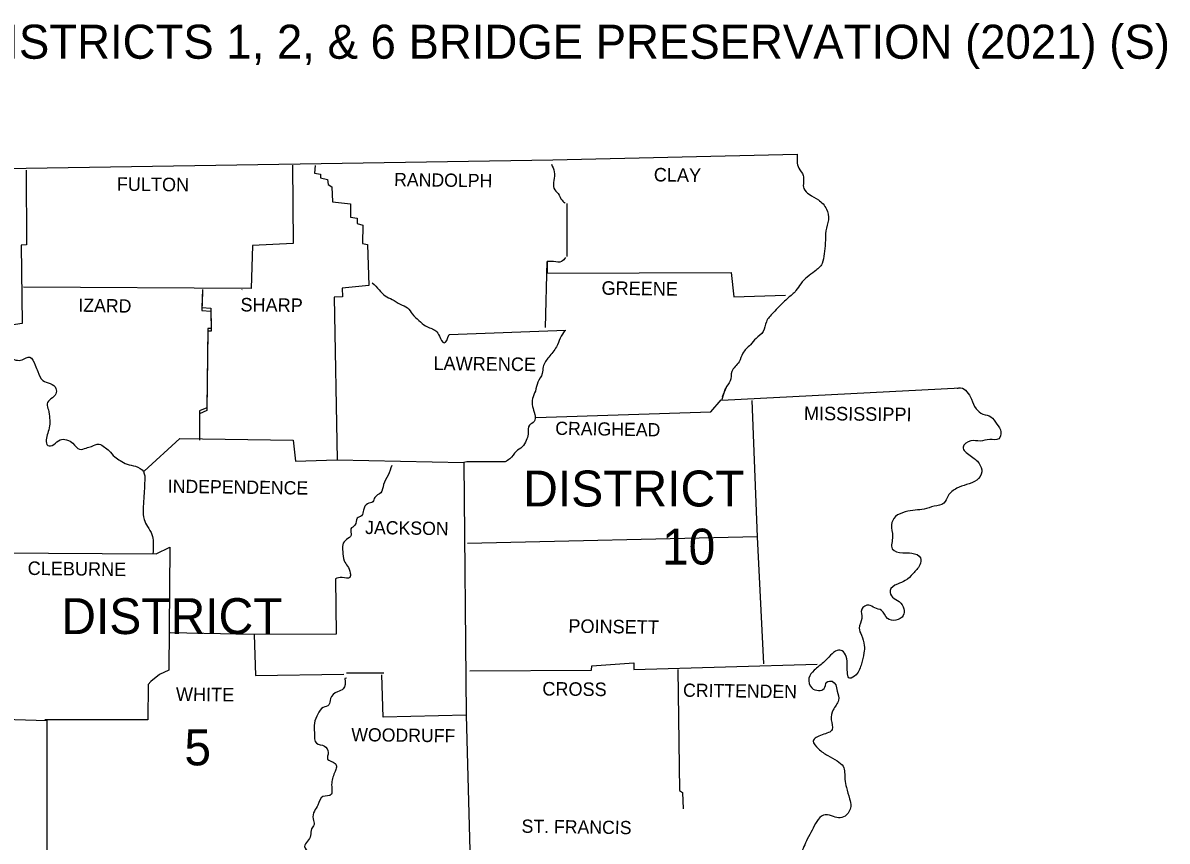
# Model space of a CAD drawing. Extents: x -31696 to 27919, y -8775 to 11152.
# Drawn here: x 13726 to 17282, y 8206 to 10749 of the extents above; entities that cross this region are included whole.
import ezdxf

# ---------------------------------------------------------------- set-up
doc = ezdxf.new("R2010")
doc.units = 0
for name, color, linetype in [('Level 1', 7, 'Continuous'), ('Level 2', 7, 'Continuous'), ('Level 3', 7, 'Continuous'), ('Level 42', 7, 'Continuous')]:
    doc.layers.add(name, color=color, linetype=linetype)

msp = doc.modelspace()

# ---------------------------------------------------------------- linework, layer by layer
at = {"layer": 'Level 1'}
for p, q in [((15897.8, 9576.2), (15909.5, 9612.4)), ((15900.7, 9588), (15912.5, 9616.3)), ((14731.5, 8728.9), (14848, 8728.9))]:
    msp.add_line(p, q, dxfattribs=at)
for points in [[(10765.1, 10295.4), (12347.2, 10294.4), (13735.5, 10297.3), (15373.4, 10322.8), (16132.6, 10340.4)], [(13735.5, 10291.4), (13737.5, 10058.6), (13720.8, 10057.6), (13723.8, 9814), (13655.3, 9804.2), (13661.2, 9738.6), (13684.6, 9708.3), (13682.7, 9631), (13549.6, 9626.1), (13544.7, 9506.8), (13423.4, 9502.9), (13417.5, 9358), (13424.4, 9346.3), (13427.3, 9115.4), (13636.7, 9101.7), (13633.8, 8586.1), (13800.1, 8581.2), (13800.1, 8056.8), (13669, 8047), (13659.2, 7931.5), (13439.1, 7930.6)], [(14564.2, 10306.1), (14566.2, 10063.5), (14439, 10056.6), (14435.1, 9923.6), (13727.7, 9927.5)], [(14634.7, 10305.1), (14631.7, 10281.7), (14651.3, 10278.7), (14650.3, 10267), (14672.8, 10262.1), (14674.8, 10246.4), (14685.5, 10239.6), (14688.5, 10192.6), (14744.3, 10186.8), (14744.3, 10144.7), (14764.8, 10141.8), (14764.8, 10125.1), (14782.4, 10120.2), (14781.4, 10063.5), (14797.1, 10060.5), (14801, 9932.4), (14717.8, 9924.5), (14718.8, 9897.2), (14693.4, 9896.2), (14702.2, 9391.3), (15096.5, 9382.5), (15103.3, 8597.8), (14846, 8591), (14841.1, 8723.1)], [(15416.4, 10187.7), (15416.4, 10022.4)], [(15349.9, 9802.2), (15354.8, 10006.7), (15354.8, 9970.5), (15927.1, 9973.5), (15935, 9897.2), (16096.4, 9903)], [(14284.4, 9920.6), (14282.4, 9863.9), (14309.8, 9861.9), (14310.8, 9799.3), (14301, 9799.3), (14297.1, 9552.8), (14274.6, 9543), (14274.6, 9460.8)], [(14284.4, 9911.8), (14282.4, 9855.1), (14309.8, 9853.1), (14310.8, 9790.5), (14301, 9790.5), (14297.1, 9543.9), (14274.6, 9534.2), (14274.6, 9452)], [(14406.7, 9918.7), (14407.7, 9919.7)], [(15050.5, 9780.7), (15413.5, 9793.4)], [(15897.8, 9576.2), (16640.4, 9614.4)], [(15320.5, 9522.4), (15863.5, 9540), (15895.8, 9577.2)], [(15991.7, 9575.3), (16008.4, 9151.6), (16027.9, 8757.3)], [(14102.4, 9356.1), (14214, 9456.9), (14566.2, 9452), (14573, 9386.4), (14701.2, 9391.3)], [(15224.6, 9384.5), (15105.3, 9384.5), (15096.5, 9382.5)], [(16008.4, 9151.6), (15107.2, 9131.1)], [(13636.7, 9101.7), (14139.6, 9098.8), (14182.6, 9119.3), (14179.7, 8736.8), (14150.4, 8724), (14123.9, 8701.5), (14115.1, 8692.7), (14114.2, 8583.2), (13794.2, 8583.2)], [(14697.3, 9021.5), (14699.2, 8849.3), (14444.9, 8848.3), (14183.6, 8853.2)], [(14444.9, 8848.3), (14448.8, 8720.1), (14723.7, 8725)], [(15115.1, 8734.8), (15492.7, 8736.8), (15493.7, 8750.5), (15624.8, 8760.2), (15624.8, 8739.7), (16194.2, 8755.4)], [(15761.8, 8739.7), (15766.7, 8363), (15775.5, 8357.1), (15778.4, 8306.3)], [(14731.5, 8712.3), (14726.6, 8711.3)], [(15103.3, 8597.8), (15118, 8061.7), (14885.1, 8060.7), (14884.2, 8039.2), (14816.7, 8035.2), (14810.8, 7923.7), (14728.6, 7923.7)]]:
    msp.add_lwpolyline(points, dxfattribs=at)
for points in [[(16132.6, 10340.4), (16137.5, 10297.3), (16151.2, 10274.8), (16153.2, 10233.7), (16169.8, 10216.1), (16198.2, 10198.5), (16223.6, 10170.1), (16229.5, 10136.9), (16221.6, 10102.6), (16219.7, 10064.5), (16215.8, 10031.2), (16209.9, 10000.9), (16186.4, 9976.4), (16163.9, 9958.8), (16143.4, 9938.2), (16128.7, 9916.7), (16103.3, 9893.2), (16077.8, 9868.8), (16057.3, 9847.3), (16036.7, 9819.9), (16026.9, 9789.5), (16004.4, 9768), (15986.8, 9748.4), (15963.3, 9722), (15951.6, 9695.6), (15929.1, 9665.3), (15924.2, 9635.9), (15909.5, 9612.4), (15908.6, 9608.5)], [(15368.5, 10310), (15377.3, 10285.6), (15376.3, 10259.2), (15376.3, 10234.7), (15389, 10218.1), (15401.7, 10197.5), (15411.5, 10188.7)], [(15412.5, 10019.5), (15399.8, 10006.7), (15375.3, 10006.7), (15354.8, 10006.7)], [(14811.8, 9941.2), (14833.3, 9918.7), (14851.9, 9900.1), (14873.4, 9889.3), (14898.8, 9874.6), (14921.3, 9862.9), (14936, 9844.3), (14956.6, 9823.8), (14977.1, 9807.1), (15009.4, 9791.5), (15020.2, 9774.9), (15034.8, 9754.3), (15050.5, 9780.7)], [(15410.5, 9792.5), (15395.9, 9769), (15384.1, 9741.6), (15360.6, 9710.3), (15343, 9679.9), (15340.1, 9659.4), (15326.4, 9632), (15318.6, 9604.6), (15309.8, 9581.1), (15309.8, 9556.7), (15316.6, 9532.2), (15314.7, 9509.7), (15300, 9498.9), (15296.1, 9470.6), (15290.2, 9451), (15277.5, 9431.4), (15258.9, 9416.8), (15239.3, 9394.2), (15224.6, 9384.5)], [(13684.6, 9708.3), (13723.8, 9701.5), (13747.3, 9710.3), (13763.9, 9684.8), (13772.7, 9665.3), (13787.4, 9636.9), (13810.9, 9628.1), (13828.5, 9612.4), (13828.5, 9595.8), (13812.8, 9580.1), (13801.1, 9564.5), (13805, 9545.9), (13808.9, 9520.5), (13808.9, 9496), (13803, 9473.5), (13798.1, 9453), (13803, 9435.3), (13821.6, 9438.3), (13841.2, 9453), (13861.7, 9453), (13881.3, 9442.2), (13901.8, 9423.6), (13922.4, 9427.5), (13939, 9432.4), (13962.5, 9439.3), (13979.1, 9430.5), (13993.8, 9418.7), (14011.4, 9400.1), (14028.1, 9388.4), (14049.6, 9377.6), (14076, 9370.8), (14100.5, 9354.1), (14104.4, 9325.8), (14103.4, 9301.3), (14101.4, 9271), (14099.5, 9237.7), (14102.4, 9205.4), (14113.2, 9183.9), (14126.9, 9158.5), (14130.8, 9135), (14129.8, 9097.8)], [(16629.6, 9613.4), (16640.4, 9614.4), (16673.7, 9579.2), (16688.3, 9549.8), (16709.9, 9533.2), (16734.3, 9524.4), (16752.9, 9501.9), (16765.6, 9477.4), (16758.8, 9455.9), (16731.4, 9453.9), (16701.1, 9449), (16671.7, 9450), (16648.2, 9430.5), (16669.8, 9404), (16698.1, 9379.6), (16706, 9353.2), (16690.3, 9327.7), (16659, 9314), (16628.7, 9302.3), (16601.3, 9278.8), (16588.5, 9256.3), (16558.2, 9246.5), (16526.9, 9237.7), (16499.5, 9234.8), (16468.2, 9228.9), (16437.9, 9214.2), (16425.2, 9188.8), (16429.1, 9152.6), (16428.1, 9114.4), (16460.4, 9101.7), (16488.8, 9100.7), (16516.1, 9086.1), (16513.2, 9064.5), (16492.7, 9037.1), (16468.2, 9015.6), (16443.7, 9004.8), (16421.2, 8984.3), (16429.1, 8963.8), (16449.6, 8950.1), (16464.3, 8927.5), (16462.3, 8907), (16438.9, 8892.3), (16413.4, 8898.2), (16394.8, 8922.7), (16373.3, 8930.5), (16354.7, 8939.3), (16333.2, 8926.6), (16333.2, 8898.2), (16325.4, 8867.9), (16332.2, 8845.4), (16341, 8814.1), (16340, 8790.6), (16332.2, 8757.3), (16315.6, 8723.1), (16296, 8712.3), (16288.2, 8749.5), (16284.3, 8779.8), (16272.5, 8797.4), (16256.9, 8798.4), (16236.3, 8783.7), (16213.8, 8761.2), (16185.4, 8736.8), (16168.8, 8712.3), (16177.6, 8682), (16199.1, 8674.1), (16215.8, 8680), (16224.6, 8699.6), (16241.2, 8702.5), (16256.9, 8672.2)], [(14872.4, 9373.7), (14860.7, 9343.4), (14847, 9314), (14838.2, 9288.6), (14819.6, 9273.9), (14813.7, 9260.2), (14797.1, 9254.3), (14784.4, 9234.8), (14778.5, 9217.2), (14764.8, 9209.3), (14757.9, 9187.8), (14745.2, 9176.1), (14746.2, 9156.5), (14731.5, 9142.8), (14719.8, 9127.1), (14719.8, 9105.6), (14724.7, 9077.2), (14734.5, 9060.6), (14743.3, 9039.1), (14742.3, 9025.4), (14717.8, 9025.4), (14697.3, 9021.5)], [(14726.6, 8711.3), (14721.7, 8679), (14703.2, 8670.2), (14681.6, 8648.7), (14676.7, 8629.1), (14659.1, 8621.3), (14642.5, 8600.8), (14631.7, 8572.4), (14631.7, 8543), (14638.6, 8509.8), (14663, 8501), (14674.8, 8481.4), (14672.8, 8460.8), (14696.3, 8447.2), (14700.2, 8435.4), (14696.3, 8422.7), (14685.5, 8386.5), (14686.5, 8362), (14684.6, 8351.3), (14658.2, 8344.4), (14642.5, 8318), (14631.7, 8299.4), (14627.8, 8275), (14630.8, 8257.3), (14622.9, 8243.6), (14620, 8223.1), (14610.2, 8205.5), (14601.4, 8188.9), (14611.2, 8169.3), (14608.3, 8155.6), (14602.4, 8134.1), (14607.3, 8127.2)], [(16256.9, 8672.2), (16260.8, 8643.8), (16244.1, 8613.5), (16238.3, 8583.2), (16241.2, 8552.8), (16209.9, 8536.2), (16182.5, 8516.6), (16198.2, 8493.1), (16227.5, 8471.6), (16256.9, 8455), (16275.5, 8438.3), (16280.3, 8398.2), (16285.2, 8372.8), (16295, 8337.6), (16298.9, 8313.1), (16281.3, 8283.8), (16260.8, 8277.9), (16239.3, 8284.7), (16213.8, 8286.7), (16193.3, 8267.1), (16178.6, 8239.7), (16163.9, 8212.3), (16153.2, 8188.9), (16142.4, 8163.4), (16120.9, 8134.1), (16094.5, 8129.2), (16063.1, 8121.3), (16044.6, 8099.8), (16047.5, 8063.6), (16065.1, 8039.2), (16078.8, 8008.8), (16088.6, 7982.4), (16083.7, 7949.1), (16070, 7924.7), (16052.4, 7910), (16044.6, 7878.7), (16031.8, 7855.2), (16020.1, 7847.4), (15996.6, 7849.3), (15971.2, 7854.2), (15949.6, 7852.3), (15929.1, 7841.5), (15908.6, 7848.4), (15887, 7871.8), (15869.4, 7889.5), (15849.9, 7896.3), (15829.3, 7885.5), (15825.4, 7853.3), (15835.2, 7820), (15844, 7775), (15835.2, 7747.6), (15832.2, 7702.6)]]:
    msp.add_spline(points, degree=3, dxfattribs=at)

# ---------------------------------------------------------------- texts
at = {"layer": 'Level 2'}
for s, height, rotation, p in [('RANDOLPH', 41.09, 359.2583, (14879.3, 10241.6)), ('CLAY', 42.06, 359.2258, (15686.5, 10256.2)), ('FULTON', 42.06, 359.4996, (14017.3, 10226.9)), ('GREENE', 42.07, 359.2361, (15524, 9904)), ('IZARD', 41.08, 358.9258, (13897.9, 9851.2)), ('SHARP', 42.06, 359.3905, (14401.8, 9852.1)), ('LAWRENCE', 42.07, 359.2678, (15001.6, 9670.2)), ('MISSISSIPPI', 42.062, 359.3097, (16153.2, 9514.6)), ('CRAIGHEAD', 41.09, 359.1159, (15380.2, 9468.6)), ('INDEPENDENCE', 41.081, 359.2187, (14175.8, 9288.6)), ('JACKSON', 41.08, 359.1352, (14789.3, 9160.4)), ('CLEBURNE', 42.06, 359.2535, (13740.4, 9033.2)), ('POINSETT', 42.06, 359.1987, (15421, 8853.6)), ('WHITE', 42.07, 359.3139, (14201.2, 8641.9)), ('CROSS', 42.06, 359.3839, (15340.1, 8658.5)), ('CRITTENDEN', 41.09, 359.213, (15777.4, 8654.6)), ('WOODRUFF', 41.08, 359.2748, (14746.2, 8516.6)), ('ST. FRANCIS', 41.081, 359.2216, (15275.5, 8231.9))]:
    msp.add_text(s, height=height, rotation=rotation, dxfattribs=at).set_placement(p)
at = {"layer": 'Level 3'}
for s, height, p in [('DISTRICT', 111.54, (15280.9, 9245.9)), ('10', 111.54, (15712, 9065.4)), ('DISTRICT', 111.54, (13845.1, 8849.3)), ('5', 111.5, (14227.7, 8441.3))]:
    msp.add_text(s, height=height, dxfattribs=at).set_placement(p)
at = {"layer": 'Level 42'}
msp.add_text('DISTRICTS 1, 2, & 6 BRIDGE PRESERVATION (2021) (S)', height=105.809, dxfattribs=at).set_placement((13572, 10637.3))

doc.saveas('drawing.dxf')
